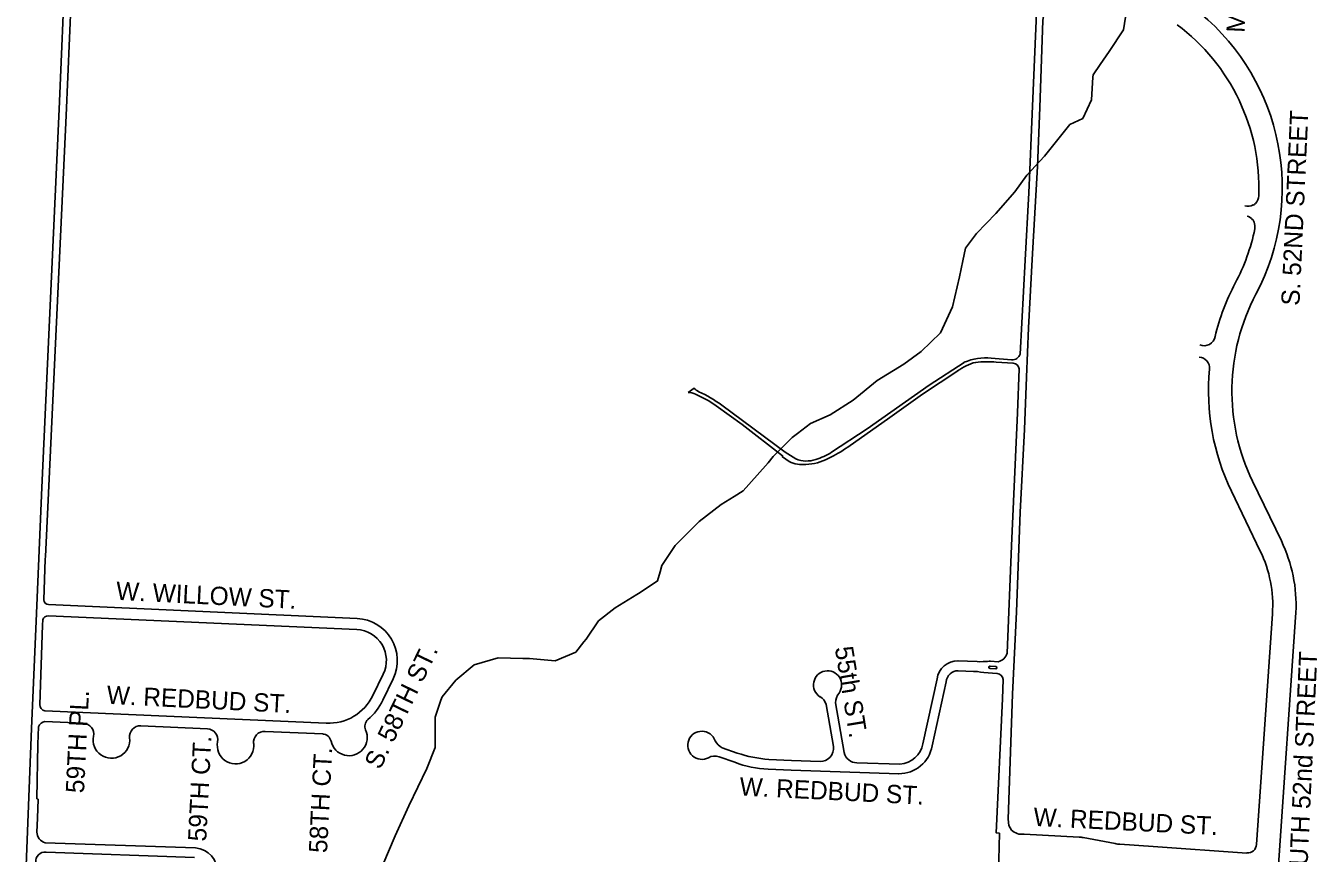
# Model space of a CAD drawing. Extents: x 0 to 712119, y 0 to 761125.
# Drawn here: x 664882 to 668416, y 731817 to 734082 of the extents above; entities that cross this region are included whole.
import ezdxf

# ---------------------------------------------------------------- set-up
doc = ezdxf.new("R2010")
doc.units = 0
for name, color, linetype in [('PAVED ROADS', 7, 'Continuous'), ('stream or creek', 7, 'Continuous'), ('street names', 7, 'Continuous')]:
    doc.layers.add(name, color=color, linetype=linetype)

msp = doc.modelspace()

# ---------------------------------------------------------------- linework, layer by layer
at = {"layer": 'PAVED ROADS'}
for points in [[(664930.7, 732510.5), (664934.4, 732621.5), (664935.1, 732629.3), (664942.3, 732783.4), (664991.9, 733836.9), (665010.6, 734261.4), (665016.7, 734436.7)], [(664990.4, 734263.5), (664972.6, 733853.8), (664925.2, 732817.8), (664909.5, 732452), (664897.5, 732157.7), (664881.5, 731759.5)], [(667578.9, 731880.2), (667572.2, 731892.8), (667570, 731910.1), (667582.2, 732251.9), (667593, 732477.7), (667603.3, 732750.3), (667614.5, 732977.2), (667620, 733120.4), (667626, 733254.8), (667636.2, 733442.1), (667650.1, 733697.3), (667657.2, 733858.6), (667665.2, 734096.7), (667686, 734235)], [(667648.6, 734138.7), (667634, 733798), (667629.3, 733687.4), (667626.4, 733624.6), (667616.9, 733440.5), (667603, 733183.4)], [(668240.6, 733591.1), (668240.4, 733591.6)], [(668246.6, 733596.1), (668247, 733595.7)], [(668239.5, 733551.6), (668239.1, 733551.3)], [(668243.2, 733544.6), (668243.6, 733544.8)], [(667450.1, 733160.7), (667354.2, 733098.2), (667184.1, 732978.3), (667086.8, 732914.6)], [(667579.5, 733167.6), (667523.9, 733172.2)], [(667537.5, 733161.5), (667583.8, 733158.3)], [(667131.5, 732928.6), (667246.3, 733009.9), (667335.5, 733073.4), (667432, 733137.5)], [(667600.5, 733143), (667595.3, 733022.8), (667579, 732658.1), (667567, 732364.4)], [(666710.3, 733089.9), (666694.1, 733078.5)], [(666771.1, 733042), (666842.3, 732990.4), (666952.9, 732904.8), (666952.4, 732901.7), (666970.6, 732888.9)], [(666989, 732896.4), (666959.4, 732914.6), (666786.7, 733043.4)], [(668181.2, 732807.8), (668260.2, 732643.9), (668260.2, 732643.9)], [(668238.8, 732835.6), (668317.8, 732671.7)], [(665788.6, 732459.2), (664943.5, 732497.5)], [(664919.8, 732223.8), (664927.6, 732440.8), (664928, 732455.7)], [(664943.7, 732466.2), (665787.3, 732429.2)], [(668293.4, 732472.2), (668249.9, 731840.4), (668249.9, 731840.4)], [(668357.7, 732475.7), (668309.3, 731771.2)], [(667542.8, 732341), (667522.2, 732342.2), (667518.4, 732342.2), (667513.5, 732342), (667510.2, 732341.9), (667501.6, 732341.4), (667492.6, 732341), (667485.1, 732341.4), (667432.8, 732343.3)], [(667433.3, 732316.4), (667475.1, 732314.2), (667486.3, 732314), (667494.7, 732312.6), (667503.5, 732311.6), (667515, 732310.2), (667527.6, 732309.3), (667540, 732308.4)], [(667536.1, 732321.7), (667520.7, 732322.6)], [(667521.1, 732329), (667536.2, 732328)], [(667536.1, 732321.7), (667536.1, 732321.7)], [(665859.9, 732307.3), (665831.7, 732248.8)], [(665858.7, 732235.7), (665887, 732294.2)], [(667375.5, 732294.1), (667336.9, 732116.4)], [(667362, 732111), (667400.6, 732285.9)], [(667556.8, 732292.5), (667554.7, 732239.4), (667537.6, 731872.1), (667546.2, 731871.5), (667543.6, 731762.3), (667538.7, 731762), (667532.2, 731616)], [(665704, 732172.7), (664933.7, 732206.6)], [(667071.6, 732223.9), (667092.2, 732108.7)], [(667121.7, 732092), (667098, 732228)], [(664933.9, 732177.1), (665038.8, 732172.8)], [(664912.1, 731874.6), (664913.4, 731912.8), (664915.2, 731964.2), (664911.9, 731966), (664914.6, 732115.3), (664916.5, 732162.7)], [(665196.6, 732165.6), (665378.5, 732157.4)], [(665536.3, 732150.3), (665694.1, 732143.1)], [(666828.8, 732090.9), (666787.8, 732105.6)], [(666778.8, 732080.9), (666822.1, 732065.6)], [(667055.3, 732067.7), (666977.5, 732070.4), (666915.1, 732073.4)], [(666913.3, 732046.8), (666975.9, 732044.3), (667270.5, 732034.4)], [(667274, 732060.2), (667155.9, 732064.3)], [(667764.7, 731860.8), (667613.9, 731868.9)], [(667862.6, 731842.8), (667775.4, 731859.4)], [(665346.2, 731831.1), (664934.5, 731845.3)], [(665343.1, 731804.9), (664936.9, 731819.3)], [(668223.3, 731817.2), (668223.3, 731817.2), (667967.2, 731834.8), (667875.6, 731841.1)]]:
    msp.add_lwpolyline(points, dxfattribs=at)
for centre, radius, start, end in [((667698.5, 733638.3), 622, 332.1376, 50.3004), ((667698.5, 733638.3), 558, 357.7868, 53.2408), ((668226.1, 733618), 30, 253.9189, 298.4432), ((668226.1, 733618), 30.5, 298.4432, 313.2209), ((668226.1, 733618), 30, 313.2209, 357.7868), ((668215.7, 733532.5), 30, 38.8817, 73.9189), ((668215.7, 733532.5), 30.5, 23.806, 38.8817), ((667698.5, 733638.3), 558, 332.1376, 348.4327), ((668215.7, 733532.5), 30, 348.4327, 23.806), ((668750.5, 733082.2), 632, 152.1376, 166.3449), ((668750.5, 733082.2), 568, 152.1376, 205.7354), ((668106.8, 733236.3), 30, 246.5718, 350.5741), ((667514.3, 733026.8), 138, 103.8857, 126.6594), ((667508.5, 733028.4), 144.7, 83.8779, 113.7865), ((667514.4, 732782.6), 379.6, 86.5073, 95.01), ((667581.5, 733190.1), 22.5, 264.9163, 342.6037), ((668091.5, 733145.1), 30, 354.5462, 87.5399), ((667582.9, 733140.6), 17.7, 7.8312, 86.9529), ((668750.5, 733082.2), 632, 174.5462, 205.7354), ((666768, 733154.3), 86.5, 228.1012, 238.6961), ((666692.1, 733028.3), 50.2, 63.3858, 87.7421), ((666602.5, 732804.3), 291.4, 54.659, 67.375), ((666546.5, 732704.1), 415.7, 54.7079, 64.8633), ((666978.5, 733093.3), 209, 288.1268, 301.2159), ((666833.5, 733373), 535, 297.1826, 303.8528), ((667010.2, 732980), 99.4, 246.4989, 273.74), ((667018.4, 732966.4), 75.9, 247.2097, 289.3083), ((667007, 733041.6), 161, 273.4688, 296.1206), ((667951.2, 732495), 407, 357.2853, 25.7354), ((667953.3, 732495.5), 340.9, 356.0664, 25.7977), ((664944.4, 732511.1), 13.6, 182.7311, 266.2689), ((664941.9, 732451.8), 14.5, 83.0758, 164.1885), ((665783.4, 732344.3), 115, 334.1919, 87.4059), ((665783.4, 732344.3), 85, 334.1919, 87.4059), ((667537, 732371.2), 30.8, 280.9061, 347.2442), ((667075.9, 732277.6), 38.5, 324.4856, 237.091), ((667432.1, 732286.1), 57.2, 89.2526, 171.9299), ((667433.4, 732283.5), 32.9, 90.0324, 175.8625), ((667520.5, 732325.8), 3.24, 78.5959, 274.4842), ((667536, 732324.9), 3.13, 272.2037, 84.9787), ((667538.8, 732290.3), 18.1, 6.8159, 86.2235), ((665710.1, 732307.5), 135, 267.4059, 334.1919), ((667038.4, 732215.2), 34.4, 14.7632, 61.0877), ((667140.1, 732228.9), 42.1, 141.22, 181.2378), ((664936.8, 732223.4), 17.1, 178.5284, 259.3559), ((665710.1, 732307.5), 165, 310.8101, 334.1919), ((664937, 732155.7), 21.6, 98.2068, 161.0908), ((665037.5, 732142.8), 30, 348.2127, 87.4059), ((665834, 732164.1), 24.5, 130.8101, 204.0795), ((665115.8, 732126.5), 50, 168.2127, 6.5991), ((665195.3, 732135.7), 30, 87.4059, 186.5991), ((665377.1, 732127.4), 30, 348.2127, 87.4059), ((665534.9, 732120.3), 30, 87.4059, 186.5991), ((665693, 732118.6), 24.5, 11.6889, 87.4059), ((665766, 732133.7), 50, 191.6889, 24.0795), ((666731.6, 732112.1), 38.5, 19.2809, 298.4215), ((665455.5, 732111.1), 50, 168.2127, 6.5991), ((666813.3, 732151.7), 52.8, 210.6224, 241.0573), ((667055.6, 732104.5), 36.8, 269.6122, 6.5848), ((667272.3, 732125.2), 90.8, 268.8228, 351.0486), ((667268.5, 732129.7), 69.7, 274.5452, 349.0105), ((666767.3, 732047.7), 35.1, 70.8965, 119.694), ((666927.8, 732348.3), 301.9, 249.4906, 267.2403), ((666945.4, 732443.6), 371.5, 251.71, 265.3241), ((667156.1, 732099.5), 35.2, 192.2681, 269.7521), ((664942.6, 731874.8), 30.6, 180.4323, 254.5648), ((667607.8, 731909.6), 41.2, 225.5781, 278.5521), ((667758.6, 731771), 90, 79.2236, 86.0664), ((664933.7, 731794.2), 25.3, 82.8534, 185.1583), ((665341.3, 731767.5), 63.8, 356.0253, 85.5939), ((667883.1, 731950.9), 110, 259.2236, 266.0664), ((668225, 731842.2), 25, 266.0662, 356.0664)]:
    msp.add_arc(centre, radius, start, end, dxfattribs=at)
at = {"layer": 'stream or creek'}
msp.add_lwpolyline([(665859, 731784.7), (665892.4, 731864), (665929.4, 731946.7), (665978.8, 732048.2), (666002.2, 732106), (666002.2, 732146.7), (666002.2, 732188.9), (666017.8, 732235.6), (666020.9, 732245.1), (666058.4, 732290.4), (666108.5, 732332.6), (666174.1, 732351.3), (666241.8, 732350.1), (666260, 732349.8), (666330.3, 732343.5), (666386.5, 732367), (666409.1, 732395.7), (666414.7, 732402.9), (666449.1, 732452.9), (666494.4, 732488.9), (666553.8, 732524.8), (666562.7, 732530.7), (666610, 732562.3), (666617.3, 732587), (666622.5, 732604.4), (666658.4, 732659.1), (666724, 732724.8), (666785, 732771.6), (666819.8, 732793.6), (666844.4, 732809.1), (666883.4, 732851.4), (666912.9, 732886), (666927.2, 732902.9), (666978.8, 732954.5), (666993.1, 732965.7), (667028.7, 732993.5), (667083.4, 733017), (667145.9, 733057.6), (667211.6, 733110.7), (667285, 733156), (667331.9, 733190.4), (667385, 733241.9), (667417.8, 733312.3), (667436.5, 733395.1), (667446.2, 733438.9), (667453.7, 733473.2), (667483.4, 733513.9), (667536.6, 733568.5), (667588.1, 733627.9), (667620.9, 733673.2), (667669.3, 733725.1), (667699.1, 733762.1), (667739.3, 733812.1), (667774.3, 733828.1), (667798.3, 733879.1), (667802, 733941.2), (667802.4, 733948.1), (667822, 733976.7), (667846.4, 734012.1), (667885.4, 734071.1), (667902.2, 734175.8)], dxfattribs=at)

# ---------------------------------------------------------------- texts
at = {"layer": 'street names'}
for s, rotation, p in [('METRO PARKWAY', 87.3557, (668217.2, 734062.6)), ('S. 52ND STREET', 87.3557, (668367.3, 733315.1)), ('W. WILLOW ST.', 357.1271, (665127.5, 732510.5)), ('S. 58TH ST.', 64.1919, (665851.2, 732043)), ('55th ST.', 279.2627, (667095.5, 732379.1)), ('SOUTH 52nd STREET', 87.3557, (668385.1, 731684.9)), ('59TH PL.', 87.1271, (665040.6, 731980.2)), ('W. REDBUD ST.', 357.1271, (665101.9, 732225.8)), ('59TH CT.', 87.1271, (665375.2, 731848.1)), ('58TH CT.', 87.1271, (665705.8, 731816.3)), ('W. REDBUD ST.', 357.1271, (666833.9, 731974.9)), ('W. REDBUD ST.', 357.1271, (667638.3, 731891.6))]:
    msp.add_text(s, height=50, rotation=rotation, dxfattribs=at).set_placement(p)

doc.saveas('drawing.dxf')
